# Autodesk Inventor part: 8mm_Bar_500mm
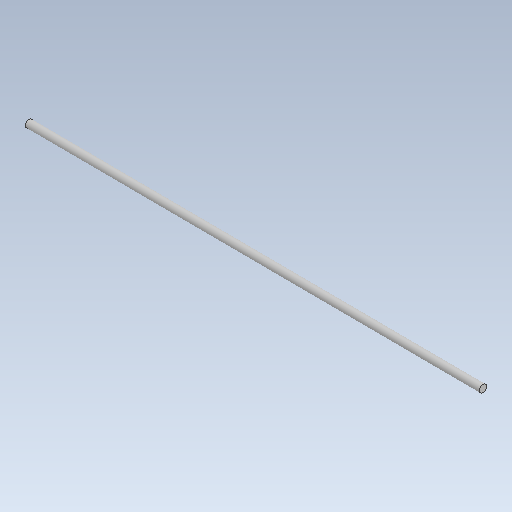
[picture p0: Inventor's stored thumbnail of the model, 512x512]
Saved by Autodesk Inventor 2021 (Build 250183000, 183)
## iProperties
Created: 2026-10
Part Number: 8mm_Bar_500mm
Material: Generic
Document SubType Name: Modeling
Designer: hp
Density: 1 g/cm^3
Appearance: Default
Author: hp
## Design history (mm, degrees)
feature "Body1"
body "Solid1"
